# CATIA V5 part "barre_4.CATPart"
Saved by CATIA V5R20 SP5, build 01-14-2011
Part number: barre_4
Publications: "diamètre pivot en K"
Bounding box of the stored display mesh (mm): x 6 to 18, y -60.961 to -27.836, z 53.986 to 86.105
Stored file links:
  M:\EU_thinkMotion\IAO_2010\iao\IAO_MMS_Groupe2\IAO_MMS_Groupe2\sdubois\sdubois\sdubois\IAO_mecanisme\barre_4.CATPart
  M:\EU_thinkMotion\IAO_2010\iao\IAO_MMS_Groupe2\IAO_MMS_Groupe2\sdubois\sdubois\sdubois\IAO_mecanisme\assembage final.CATProduct
  M:\EU_thinkMotion\IAO_2010\iao\IAO_MMS_Groupe2\IAO_MMS_Groupe2\sdubois\sdubois\sdubois\IAO_mecanisme\squelette_4.CATPart
  M:\EU_thinkMotion\IAO_2010\iao\IAO_MMS_Groupe2\IAO_MMS_Groupe2\sdubois\sdubois\sdubois\IAO_mecanisme\bati_0.CATPart
  M:\EU_thinkMotion\IAO_2010\iao\IAO_MMS_Groupe2\IAO_MMS_Groupe2\sdubois\sdubois\sdubois\IAO_mecanisme\roue_1.CATPart
  M:\EU_thinkMotion\IAO_2010\iao\IAO_MMS_Groupe2\IAO_MMS_Groupe2\sdubois\sdubois\sdubois\IAO_mecanisme\barre_3.CATPart
  M:\EU_thinkMotion\IAO_2010\iao\IAO_MMS_Groupe2\IAO_MMS_Groupe2\sdubois\sdubois\sdubois\IAO_mecanisme\barre_6.CATPart
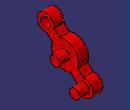
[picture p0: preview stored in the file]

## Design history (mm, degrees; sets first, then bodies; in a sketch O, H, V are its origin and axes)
Parameters
  `diamètre pivot en K` = 6 mm
External parameters (linked from other documents)
  External.largeur_barre = 6 mm
  `External.diamètre pivot en F` = 6 mm
  `External.diamètre trou oblong 'd'` = 6 mm
Set1
  Plane1 to Plane4: linked copy from another document
  Point1 to Point5: linked copy from another document
  DatumSurface1: linked copy from another document
  Line1: linked copy from another document
Set2
  Point6: type Center, Curve edge [face of Pad6 from Sketch7.A1 | end face of Pad6]
Body1 (main body)
  Sketch1 on Plane1, origin (12, 0, 0), H (0, 1, 0), V (0, 0, 1)
    line L1 (-53.8873, 83.2727) -> (-30.7627, 61.1536)
    point P1 (-53.8873, 83.2727)
    point P2 (-30.7627, 61.1536)
    line L2 (-30.7627, 61.1536) -> (-34.91, 56.8178)
    point P3 (-30.7627, 61.1536)
    point P4 (-34.91, 56.8178)
    line L3 (-34.91, 56.8178) -> (-58.0346, 78.9368)
    point P5 (-34.91, 56.8178)
    point P6 (-58.0346, 78.9368)
    line L4 (-53.8873, 83.2727) -> (-58.0346, 78.9368)
    point P7 (-53.8873, 83.2727)
    point P8 (-58.0346, 78.9368)
    reference intersected line E1 through (3.8535, 23.8913) direction (-0.7226, 0.6912) from Plane2
    reference intersected line E2 through (3.8535, 23.8913) direction (-0.7226, 0.6912) from Plane2
    reference intersected line E3 through (-65.0258, 25.3329) direction (0.6912, 0.7226) from Plane3
    reference intersected line E4 through (-96.9829, 38.2179) direction (0.6912, 0.7226) from Plane4
    reference projected point E5 (-42.325, 72.2132) from Point1
    reference projected point E6 (-46.4723, 67.8773) from Point2
    reference intersected line E7 through (-65.0258, 25.3329) direction (0.6912, 0.7226) from Plane3
    reference intersected line E8 through (-96.9829, 38.2179) direction (0.6912, 0.7226) from Plane4
    reference intersected line E9 through (-96.9829, 38.2179) direction (0.6912, 0.7226) from Plane4
    reference intersected line E10 through (-65.0258, 25.3329) direction (0.6912, 0.7226) from Plane3
    distance L1 E5 = 0
    distance E6 L3 = 0
    distance P2 E7 = 0
    distance P1 E8 = 0
    distance P6 E9 = 0
    distance P5 E10 = 0
    distance P3 P2 = 0
    distance P4 L3 = 0
    distance P7 P1 = 0
    distance P8 P6 = 0
    parallelism: L1 E1, L3 E2, L2 E3, L4 E4
  Sketch2 on Plane1, origin (12, 0, 0), H (0, 1, 0), V (0, 0, 1)
    circle A1 centre (-55.9609, 81.1048) radius 5
    point P1 (-55.9609, 81.1048)
    reference projected point E1 (-55.9609, 81.1048) from Point3
    distance P1 E1 = 0
    radius A1 = 5
  Sketch3 on Plane1, origin (12, 0, 0), H (0, 1, 0), V (0, 0, 1)
    circle A1 centre (-44.3986, 70.0452) radius 8
    point P1 (-44.3986, 70.0452)
    reference projected point E1 (-44.3986, 70.0452) from Point4
    distance P1 E1 = 0
    radius A1 = 8
  Sketch4 on Plane1, origin (12, 0, 0), H (0, 1, 0), V (0, 0, 1)
    circle A1 centre (-32.8363, 58.9857) radius 5
    point P1 (-32.8363, 58.9857)
    reference projected point E1 (-32.8363, 58.9857) from Point5
    distance P1 E1 = 0
    radius A1 = 5
  Sketch5 on Plane1, origin (12, 0, 0), H (0, 1, 0), V (0, 0, 1)
    circle A1 centre (-55.9609, 81.1048) radius 3
    point P1 (-55.9609, 81.1048)
    reference projected point E1 (-55.9609, 81.1048) from Point3
    radius A1 = 3 {= `External.diamètre pivot en F` /2}
    distance P1 E1 = 0
  Sketch6 on Plane1, origin (12, 0, 0), H (0, 1, 0), V (0, 0, 1)
    circle A1 centre (-44.3986, 70.0452) radius 3
    point P1 (-44.3986, 70.0452)
    reference projected point E1 (-44.3986, 70.0452) from Point4
    point P2 (-32.8363, 58.9857)
    reference projected point E2 (-32.8363, 58.9857) from Point5
    radius A1 = 3 {= `diamètre pivot en K` /2}
    distance P1 E1 = 0
    distance P2 E2 = 0
  Pad1: profile Sketch3, direction (1, 0, 0), length 0 {= 2*External.largeur_barre -12mm}, opposite side length 6 {= 12mm-External.largeur_barre}
  Pad2: profile Sketch2, direction (1, 0, 0), length 0 {= 2*External.largeur_barre -12mm}, opposite side length 6 {= 12mm-External.largeur_barre}
  Pad3: profile Sketch4, direction (1, 0, 0), length 0 {= 2*External.largeur_barre -12mm}, opposite side length 6 {= 12mm-External.largeur_barre}
  Pad4: profile Sketch6, direction (1, 0, 0), length 6 {= 3*External.largeur_barre -12mm}, opposite side length 6 {= 12mm-External.largeur_barre}
  Pad5: profile Sketch1, direction (1, 0, 0), length 0 {= 2*External.largeur_barre -12mm}, opposite side length 6 {= 12mm-External.largeur_barre}
  Pocket1: profile Sketch5, direction (1, 0, 0), length 0 {= 2*External.largeur_barre -12mm}, opposite side length 6 {= 12mm-External.largeur_barre}
  Sketch7 on face of Pad5, origin (12, 0, 0), H (0, 1, 0), V (0, 0, 1)
    circle A1 centre (-32.8363, 58.9857) radius 3
    point P1 (-32.8363, 58.9857)
    reference projected point E1 (-32.8363, 58.9857) from Line1
    distance P1 E1 = 0
    radius A1 = 3 {= `External.diamètre trou oblong 'd'` /2}
  Pad6: profile Sketch7, direction (1, 0, 0), length 6 {= External.largeur_barre}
